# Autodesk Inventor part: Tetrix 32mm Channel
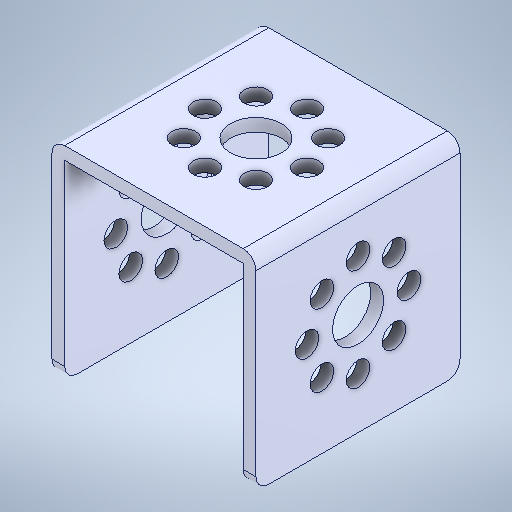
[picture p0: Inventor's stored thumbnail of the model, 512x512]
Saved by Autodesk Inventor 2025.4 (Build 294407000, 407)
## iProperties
Created: 2021-10
Part Number: Tetrix 32mm Channel
Material: Genérico
Document SubType Name: Modeling
Designer: usuario
Density: 1 g/cm^3
Appearance: Valor por defecto
Author: usuario
Sending System: SolidWorks 2016
Last Author: LENOVO
Last Saved: 2021-10-21
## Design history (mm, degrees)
fillet "Fillet1"
node "Plane1"
node "Sólido1"
